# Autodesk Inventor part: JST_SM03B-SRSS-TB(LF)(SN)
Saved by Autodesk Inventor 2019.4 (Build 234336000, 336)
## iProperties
Created: 2021-02
Part Number: JST_SM03B-SRSS-TB(LF)(SN)
Material: Generic
Document SubType Name: Modeling
Designer: Administrator
Density: 1 g/cm^3
Appearance: Default
Title: JST_SM03B-SRSS-TB(LF)(SN)
Author: Administrator
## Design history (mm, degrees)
feature "Body1"
body "Solid1"
